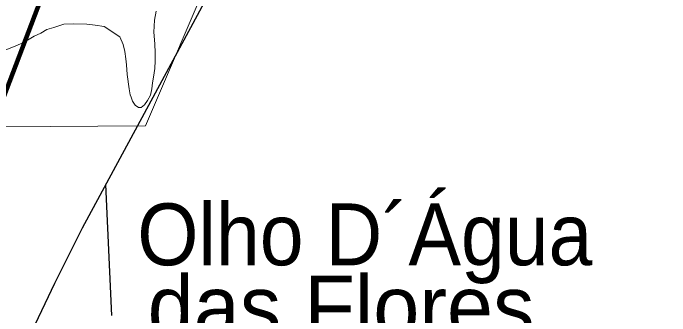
# Model space of a CAD drawing. Extents: x 553962 to 842807, y 8883888 to 9032388.
# Drawn here: x 686402 to 691702, y 8946464 to 8948911 of the extents above; entities that cross this region are included whole.
import ezdxf

# ---------------------------------------------------------------- set-up
doc = ezdxf.new("R2010")
doc.units = 0
doc.header["$LTSCALE"] = 160
for name, color, linetype, lineweight in [('15', 7, 'Continuous', 25), ('27', 7, 'Continuous', 90), ('4', 7, 'Continuous', 13)]:
    doc.layers.add(name, color=color, linetype=linetype, lineweight=lineweight)
doc.layers.add('29', color=7, linetype='Continuous')

msp = doc.modelspace()

# ---------------------------------------------------------------- linework, layer by layer
at = {"layer": '15'}
msp.add_line((687197.4, 8946467.8), (687150.2, 8947525.7), dxfattribs=at)
for points in [[(686961.1, 8947176.1), (688051.1, 8949196.4), (690022.8, 8953729), (690920.6, 8955829.2)], [(685809.3, 8944882.1), (685913.1, 8945087.1), (686095.5, 8945430.2), (686141.8, 8945504.8), (686252.8, 8945715.1), (686434, 8946034.8), (686467.2, 8946134), (686554.8, 8946343.8), (686737.9, 8946728.7), (686961.1, 8947176.1)]]:
    msp.add_lwpolyline(points, dxfattribs=at)
at = {"layer": '27'}
msp.add_line((688209.7, 8953202.5), (684981, 8944688.2), dxfattribs=at)
for points in [[(637260.6, 8972975.8), (641524.5, 8971056.2), (652526.1, 8965412.7), (653164.3, 8965062.8), (670790.5, 8953770.1), (686194, 8943929.9), (696283.3, 8937647.1)], [(694874, 8947402.7), (694491.4, 8947729), (693981.6, 8948105.1), (692654.2, 8949437.3), (691811.8, 8950292), (691552.9, 8951277.6), (691093.4, 8951755.3), (689976, 8951721.8), (689441.2, 8951996.3), (689158.9, 8952576.6), (688699.5, 8953029), (687605.5, 8953400.8), (685873.4, 8954400.8), (684752.3, 8955101.5), (681638, 8958243.7), (680641.1, 8959527.7), (679425.4, 8960995.9)]]:
    msp.add_spline(points, degree=3, dxfattribs=at)
at = {"layer": '4'}
for points in [[(685550.2, 8947987.8), (687469.9, 8947999.3), (688024.9, 8949298.9)], [(687556.7, 8948926.2), (687542.7, 8948853.1), (687538, 8948756.8), (687546.2, 8948663.9), (687547.3, 8948589), (687548.9, 8948524.3), (687544.2, 8948462.3), (687535.4, 8948392.8), (687527.4, 8948346.2), (687520.6, 8948298.2), (687511.3, 8948249), (687486.9, 8948205.5), (687461.6, 8948170.9), (687434.1, 8948147.7), (687412.5, 8948147.2), (687386.6, 8948165.9), (687366.2, 8948199.6), (687353.3, 8948231.8), (687347.6, 8948249.7), (687339.2, 8948299.5), (687323, 8948414.2), (687318.1, 8948491.8), (687310.9, 8948540.3), (687304.2, 8948600.1), (687289.6, 8948656.5), (687262.6, 8948718.3), (687136.2, 8948802.7), (687063, 8948812.9), (686997.3, 8948821.5), (686892.1, 8948824), (686812.1, 8948820.4), (686731.2, 8948794.1), (686673.6, 8948778.4), (686625.6, 8948749.6), (686572.7, 8948723.6), (686518.3, 8948691.2), (686460.2, 8948662.8), (686406, 8948638.1), (686317.3, 8948603.2)], [(687323, 8948414.2), (687339.2, 8948299.5), (687347.6, 8948249.7), (687353.3, 8948231.8), (687366.2, 8948199.6), (687386.6, 8948165.9), (687412.5, 8948147.2), (687434.1, 8948147.7), (687461.6, 8948170.9), (687486.9, 8948205.5), (687511.3, 8948249), (687520.6, 8948298.2), (687527.4, 8948346.2), (687535.4, 8948392.8), (687544.2, 8948462.3), (687548.9, 8948524.3), (687547.3, 8948589), (687546.2, 8948663.9), (687538, 8948756.8), (687542.7, 8948853.1), (687556.7, 8948926.2)], [(686317.3, 8948603.2), (686406, 8948638.1), (686460.2, 8948662.8), (686518.3, 8948691.2), (686572.7, 8948723.6), (686625.6, 8948749.6), (686673.6, 8948778.4), (686731.2, 8948794.1), (686812.1, 8948820.4), (686892.1, 8948824), (686997.3, 8948821.5), (687063, 8948812.9), (687136.2, 8948802.7), (687262.6, 8948718.3), (687289.6, 8948656.5), (687304.2, 8948600.1), (687310.9, 8948540.3), (687318.1, 8948491.8), (687323, 8948414.2)]]:
    msp.add_lwpolyline(points, dxfattribs=at)

# ---------------------------------------------------------------- texts
at = {"layer": '29', "width": 0.95}
msp.add_text('Olho D´Água', height=500, dxfattribs=at).set_placement((687404, 8946873))
at = {"layer": '29'}
msp.add_text('das Flores', height=500, dxfattribs=at).set_placement((687487.5, 8946289.8))

doc.saveas('drawing.dxf')
